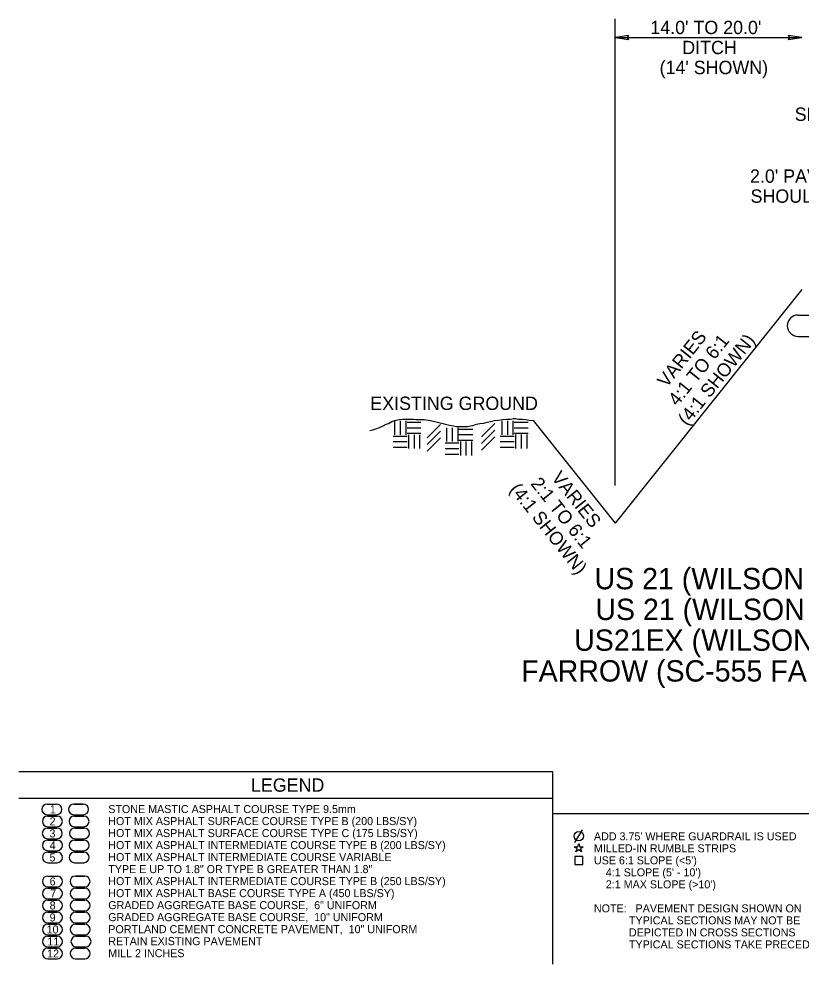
# Model space of a CAD drawing. Extents: x 2003207 to 2014043, y 843846 to 860154.
# Drawn here: x 2013805.7 to 2013864.3, y 844566 to 844636.8 of the extents above; entities that cross this region are included whole.
import ezdxf

# ---------------------------------------------------------------- set-up
doc = ezdxf.new("R2010")
doc.units = 0
for name, color, linetype in [('RD_EX_Road', 7, 'Continuous'), ('RD_EX_Road_txCode', 7, 'Continuous'), ('RD_QTY_ConcPave', 7, 'Continuous'), ('RD_QTY_Intermediate', 7, 'Continuous'), ('RD_QTY_Milling', 7, 'Continuous'), ('RD_QTY_PermVeg', 7, 'Continuous'), ('RD_QTY_Surf_Course', 7, 'Continuous'), ('RD_SHT_Bndy', 7, 'Continuous'), ('RD_TX_Misc2', 7, 'Continuous'), ('RD_TX_TypSect', 7, 'Continuous'), ('RD_XS_ExGround', 7, 'Continuous')]:
    doc.layers.add(name, color=color, linetype=linetype)

msp = doc.modelspace()

# ---------------------------------------------------------------- linework, layer by layer
at = {"layer": 'RD_EX_Road'}
for p, q in [((2013810.723, 844568.087), (2013810.023, 844568.087)), ((2013810.661, 844567.187), (2013809.961, 844567.187)), ((2013810.023, 844567.287), (2013810.723, 844567.287)), ((2013809.961, 844566.387), (2013810.661, 844566.387))]:
    msp.add_line(p, q, dxfattribs=at)
for centre, start, end in [((2013810.023, 844567.687), 90, 270), ((2013810.723, 844567.687), 270, 90), ((2013809.961, 844566.787), 90, 270), ((2013810.661, 844566.787), 270, 90)]:
    msp.add_arc(centre, 0.4, start, end, dxfattribs=at)
at = {"layer": 'RD_EX_Road_txCode'}
msp.add_line((2013847.384, 844575.107), (2013847.95, 844576.05), dxfattribs=at)
for points in [[(2013847.335, 844574.786), (2013847.589, 844574.786), (2013847.667, 844575.028), (2013847.746, 844574.786), (2013848, 844574.786), (2013847.795, 844574.637), (2013847.873, 844574.395), (2013847.667, 844574.544), (2013847.462, 844574.395), (2013847.54, 844574.637)], [(2013847.367, 844573.452), (2013847.967, 844573.452), (2013847.967, 844574.052), (2013847.367, 844574.052)]]:
    msp.add_lwpolyline(points, close=True, dxfattribs=at)
msp.add_circle((2013847.667, 844575.578), 0.35, dxfattribs=at)
at = {"layer": 'RD_QTY_ConcPave'}
for p, q in [((2013810.661, 844570.787), (2013809.961, 844570.787)), ((2013809.961, 844569.987), (2013810.661, 844569.987)), ((2013810.661, 844569.887), (2013809.961, 844569.887)), ((2013809.961, 844569.087), (2013810.661, 844569.087)), ((2013810.661, 844568.987), (2013809.961, 844568.987)), ((2013809.961, 844568.187), (2013810.661, 844568.187))]:
    msp.add_line(p, q, dxfattribs=at)
for centre, start, end in [((2013809.961, 844570.387), 90, 270), ((2013810.661, 844570.387), 270, 90), ((2013809.961, 844569.487), 90, 270), ((2013810.661, 844569.487), 270, 90), ((2013809.961, 844568.587), 90, 270), ((2013810.661, 844568.587), 270, 90)]:
    msp.add_arc(centre, 0.4, start, end, dxfattribs=at)
at = {"layer": 'RD_QTY_Intermediate'}
for p, q in [((2013810.582, 844575.287), (2013809.882, 844575.287)), ((2013809.882, 844574.487), (2013810.582, 844574.487)), ((2013810.582, 844574.387), (2013809.882, 844574.387)), ((2013809.882, 844573.587), (2013810.582, 844573.587)), ((2013810.65, 844572.587), (2013809.95, 844572.587)), ((2013809.95, 844571.787), (2013810.65, 844571.787)), ((2013810.661, 844571.687), (2013809.961, 844571.687)), ((2013809.961, 844570.887), (2013810.661, 844570.887))]:
    msp.add_line(p, q, dxfattribs=at)
for centre, start, end in [((2013809.882, 844574.887), 90, 270), ((2013810.582, 844574.887), 270, 90), ((2013809.882, 844573.987), 90, 270), ((2013810.582, 844573.987), 270, 90), ((2013809.95, 844572.187), 90, 270), ((2013810.65, 844572.187), 270, 90), ((2013809.961, 844571.287), 90, 270), ((2013810.661, 844571.287), 270, 90)]:
    msp.add_arc(centre, 0.4, start, end, dxfattribs=at)
at = {"layer": 'RD_QTY_Milling'}
for p, q in [((2013810.661, 844567.187), (2013809.961, 844567.187)), ((2013809.961, 844566.387), (2013810.661, 844566.387))]:
    msp.add_line(p, q, dxfattribs=at)
for centre, start, end in [((2013809.961, 844566.787), 90, 270), ((2013810.661, 844566.787), 270, 90)]:
    msp.add_arc(centre, 0.4, start, end, dxfattribs=at)
at = {"layer": 'RD_QTY_PermVeg'}
for p in [(2013864.392, 844616.536), (2013844.245, 844606.72)]:
    msp.add_line(p, (2013850.392, 844599.036), dxfattribs=at)
at = {"layer": 'RD_QTY_Surf_Course'}
for p, q in [((2013810.542, 844577.987), (2013809.842, 844577.987)), ((2013809.842, 844577.187), (2013810.542, 844577.187)), ((2013810.576, 844577.087), (2013809.876, 844577.087)), ((2013809.876, 844576.287), (2013810.576, 844576.287)), ((2013810.61, 844576.187), (2013809.91, 844576.187)), ((2013809.91, 844575.387), (2013810.61, 844575.387))]:
    msp.add_line(p, q, dxfattribs=at)
for centre, start, end in [((2013809.842, 844577.587), 90, 270), ((2013810.542, 844577.587), 270, 90), ((2013809.876, 844576.687), 90, 270), ((2013810.576, 844576.687), 270, 90), ((2013809.91, 844575.787), 90, 270), ((2013810.61, 844575.787), 270, 90)]:
    msp.add_arc(centre, 0.4, start, end, dxfattribs=at)
at = {"layer": 'RD_SHT_Bndy'}
for p, q in [((2013845.721, 844580.41), (2013805.721, 844580.41)), ((2013845.721, 844578.41), (2013845.721, 844580.41)), ((2013845.721, 844578.41), (2013805.721, 844578.41)), ((2013845.721, 844565.992), (2013845.721, 844578.41)), ((2013868.755, 844577.242), (2013845.755, 844577.242))]:
    msp.add_line(p, q, dxfattribs=at)
at = {"layer": 'RD_TX_Misc2'}
for p, q in [((2013864.098, 844614.63), (2013865.498, 844614.63)), ((2013864.098, 844613.03), (2013865.498, 844613.03)), ((2013807.842, 844577.987), (2013808.542, 844577.987)), ((2013809.842, 844577.987), (2013810.542, 844577.987)), ((2013807.842, 844577.187), (2013808.542, 844577.187)), ((2013807.876, 844577.087), (2013808.576, 844577.087)), ((2013809.842, 844577.187), (2013810.542, 844577.187)), ((2013809.876, 844577.087), (2013810.576, 844577.087)), ((2013807.871, 844576.187), (2013808.571, 844576.187)), ((2013807.876, 844576.287), (2013808.576, 844576.287)), ((2013809.876, 844576.287), (2013810.576, 844576.287)), ((2013809.91, 844576.187), (2013810.61, 844576.187)), ((2013807.871, 844575.387), (2013808.571, 844575.387)), ((2013807.882, 844575.287), (2013808.582, 844575.287)), ((2013809.882, 844575.287), (2013810.582, 844575.287)), ((2013809.91, 844575.387), (2013810.61, 844575.387)), ((2013807.882, 844574.487), (2013808.582, 844574.487)), ((2013807.882, 844574.387), (2013808.582, 844574.387)), ((2013809.882, 844574.487), (2013810.582, 844574.487)), ((2013809.882, 844574.387), (2013810.582, 844574.387)), ((2013807.882, 844573.587), (2013808.582, 844573.587)), ((2013809.882, 844573.587), (2013810.582, 844573.587)), ((2013807.882, 844572.587), (2013808.582, 844572.587)), ((2013809.95, 844572.587), (2013810.65, 844572.587)), ((2013807.882, 844571.787), (2013808.582, 844571.787)), ((2013807.882, 844571.687), (2013808.582, 844571.687)), ((2013809.95, 844571.787), (2013810.65, 844571.787)), ((2013809.961, 844571.687), (2013810.661, 844571.687)), ((2013807.882, 844570.887), (2013808.582, 844570.887)), ((2013807.882, 844570.787), (2013808.582, 844570.787)), ((2013809.961, 844570.887), (2013810.661, 844570.887)), ((2013809.961, 844570.787), (2013810.661, 844570.787)), ((2013807.882, 844569.987), (2013808.582, 844569.987)), ((2013809.961, 844569.987), (2013810.661, 844569.987)), ((2013807.882, 844569.887), (2013808.582, 844569.887)), ((2013809.961, 844569.887), (2013810.661, 844569.887)), ((2013807.882, 844569.087), (2013808.582, 844569.087)), ((2013807.882, 844568.987), (2013808.582, 844568.987)), ((2013809.961, 844569.087), (2013810.661, 844569.087)), ((2013809.961, 844568.987), (2013810.661, 844568.987)), ((2013807.882, 844568.187), (2013808.582, 844568.187)), ((2013807.882, 844568.087), (2013808.582, 844568.087)), ((2013809.961, 844568.187), (2013810.661, 844568.187)), ((2013810.023, 844568.087), (2013810.723, 844568.087)), ((2013807.882, 844567.287), (2013808.582, 844567.287)), ((2013807.882, 844567.187), (2013808.582, 844567.187)), ((2013809.961, 844567.187), (2013810.661, 844567.187)), ((2013810.023, 844567.287), (2013810.723, 844567.287)), ((2013807.882, 844566.387), (2013808.582, 844566.387)), ((2013809.961, 844566.387), (2013810.661, 844566.387))]:
    msp.add_line(p, q, dxfattribs=at)
for centre, radius, start, end in [((2013864.098, 844613.83), 0.8, 90, 270), ((2013807.842, 844577.587), 0.4, 90, 270), ((2013808.542, 844577.587), 0.4, 270, 90), ((2013809.842, 844577.587), 0.4, 90, 270), ((2013810.542, 844577.587), 0.4, 270, 90), ((2013807.876, 844576.687), 0.4, 90, 270), ((2013808.576, 844576.687), 0.4, 270, 90), ((2013809.876, 844576.687), 0.4, 90, 270), ((2013810.576, 844576.687), 0.4, 270, 90), ((2013807.871, 844575.787), 0.4, 90, 270), ((2013808.571, 844575.787), 0.4, 270, 90), ((2013809.91, 844575.787), 0.4, 90, 270), ((2013810.61, 844575.787), 0.4, 270, 90), ((2013807.882, 844574.887), 0.4, 90, 270), ((2013808.582, 844574.887), 0.4, 270, 90), ((2013809.882, 844574.887), 0.4, 90, 270), ((2013810.582, 844574.887), 0.4, 270, 90), ((2013807.882, 844573.987), 0.4, 90, 270), ((2013808.582, 844573.987), 0.4, 270, 90), ((2013809.882, 844573.987), 0.4, 90, 270), ((2013810.582, 844573.987), 0.4, 270, 90), ((2013807.882, 844572.187), 0.4, 90, 270), ((2013808.582, 844572.187), 0.4, 270, 90), ((2013809.95, 844572.187), 0.4, 90, 270), ((2013810.65, 844572.187), 0.4, 270, 90), ((2013807.882, 844571.287), 0.4, 90, 270), ((2013808.582, 844571.287), 0.4, 270, 90), ((2013809.961, 844571.287), 0.4, 90, 270), ((2013810.661, 844571.287), 0.4, 270, 90), ((2013807.882, 844570.387), 0.4, 90, 270), ((2013808.582, 844570.387), 0.4, 270, 90), ((2013809.961, 844570.387), 0.4, 90, 270), ((2013810.661, 844570.387), 0.4, 270, 90), ((2013807.882, 844569.487), 0.4, 90, 270), ((2013808.582, 844569.487), 0.4, 270, 90), ((2013809.961, 844569.487), 0.4, 90, 270), ((2013810.661, 844569.487), 0.4, 270, 90), ((2013807.882, 844568.587), 0.4, 90, 270), ((2013808.582, 844568.587), 0.4, 270, 90), ((2013809.961, 844568.587), 0.4, 90, 270), ((2013810.661, 844568.587), 0.4, 270, 90), ((2013807.882, 844567.687), 0.4, 90, 270), ((2013808.582, 844567.687), 0.4, 270, 90), ((2013810.023, 844567.687), 0.4, 90, 270), ((2013810.723, 844567.687), 0.4, 270, 90), ((2013807.882, 844566.787), 0.4, 90, 270), ((2013808.582, 844566.787), 0.4, 270, 90), ((2013809.961, 844566.787), 0.4, 90, 270), ((2013810.661, 844566.787), 0.4, 270, 90)]:
    msp.add_arc(centre, radius, start, end, dxfattribs=at)
at = {"layer": 'RD_TX_TypSect'}
for p, q in [((2013850.392, 844601.863), (2013850.392, 844636.824)), ((2013850.392, 844635.433), (2013864.392, 844635.433))]:
    msp.add_line(p, q, dxfattribs=at)
for points in [[(2013850.392, 844635.433), (2013851.431, 844635.283), (2013851.271, 844635.433), (2013851.431, 844635.583)], [(2013864.392, 844635.433), (2013863.354, 844635.583), (2013863.514, 844635.433), (2013863.354, 844635.283)]]:
    msp.add_lwpolyline(points, close=True, dxfattribs=at)
at = {"layer": 'RD_XS_ExGround'}
for p, q in [((2013833.875, 844606.7), (2013833.875, 844605.658)), ((2013834.292, 844606.7), (2013834.292, 844605.658)), ((2013834.709, 844606.7), (2013834.709, 844605.658)), ((2013834.805, 844606.603), (2013835.847, 844606.603)), ((2013834.805, 844606.186), (2013835.847, 844606.186)), ((2013836.311, 844605.441), (2013837.311, 844606.441)), ((2013837.766, 844606.186), (2013837.766, 844605.145)), ((2013838.182, 844606.186), (2013838.182, 844605.145)), ((2013838.599, 844606.186), (2013838.599, 844605.145)), ((2013840.379, 844605.514), (2013841.379, 844606.514)), ((2013841.902, 844606.705), (2013841.902, 844605.663)), ((2013842.319, 844606.705), (2013842.319, 844605.663)), ((2013842.735, 844606.705), (2013842.735, 844605.663)), ((2013842.832, 844606.608), (2013843.873, 844606.608)), ((2013842.832, 844606.191), (2013843.873, 844606.191)), ((2013833.763, 844605.561), (2013834.805, 844605.561)), ((2013834.805, 844605.77), (2013835.847, 844605.77)), ((2013834.909, 844605.666), (2013834.909, 844604.624)), ((2013835.326, 844605.666), (2013835.326, 844604.624)), ((2013835.743, 844605.666), (2013835.743, 844604.624)), ((2013836.311, 844604.941), (2013837.311, 844605.941)), ((2013836.311, 844604.441), (2013837.311, 844605.441)), ((2013838.696, 844606.089), (2013839.737, 844606.089)), ((2013838.696, 844605.673), (2013839.737, 844605.673)), ((2013840.379, 844605.014), (2013841.379, 844606.014)), ((2013840.379, 844604.514), (2013841.379, 844605.514)), ((2013841.79, 844605.566), (2013842.832, 844605.566)), ((2013842.832, 844605.775), (2013843.873, 844605.775)), ((2013842.936, 844605.67), (2013842.936, 844604.629)), ((2013843.353, 844605.67), (2013843.353, 844604.629)), ((2013843.769, 844605.67), (2013843.769, 844604.629)), ((2013833.763, 844605.145), (2013834.805, 844605.145)), ((2013833.763, 844604.728), (2013834.805, 844604.728)), ((2013837.654, 844605.048), (2013838.696, 844605.048)), ((2013838.696, 844605.256), (2013839.737, 844605.256)), ((2013838.8, 844605.152), (2013838.8, 844604.11)), ((2013839.216, 844605.152), (2013839.216, 844604.11)), ((2013839.633, 844605.152), (2013839.633, 844604.11)), ((2013841.79, 844605.15), (2013842.832, 844605.15)), ((2013841.79, 844604.733), (2013842.832, 844604.733)), ((2013837.654, 844604.631), (2013838.696, 844604.631)), ((2013837.654, 844604.214), (2013838.696, 844604.214))]:
    msp.add_line(p, q, dxfattribs=at)
msp.add_lwpolyline([(2013832.019, 844605.988), (2013832.239, 844606.024), (2013832.459, 844606.098), (2013832.751, 844606.208), (2013833.008, 844606.317), (2013833.227, 844606.464), (2013833.41, 844606.501), (2013833.667, 844606.647), (2013833.886, 844606.72), (2013834.216, 844606.794), (2013834.472, 844606.83), (2013834.765, 844606.83), (2013835.094, 844606.83), (2013835.277, 844606.83), (2013835.46, 844606.794), (2013835.68, 844606.794), (2013835.899, 844606.794), (2013836.082, 844606.794), (2013836.375, 844606.757), (2013836.558, 844606.72), (2013836.888, 844606.647), (2013837.181, 844606.574), (2013837.473, 844606.501), (2013837.656, 844606.464), (2013837.986, 844606.391), (2013838.279, 844606.317), (2013838.498, 844606.281), (2013838.681, 844606.281), (2013838.901, 844606.281), (2013839.121, 844606.281), (2013839.34, 844606.281), (2013839.56, 844606.317), (2013839.743, 844606.354), (2013839.999, 844606.464), (2013840.255, 844606.501), (2013840.548, 844606.537), (2013840.804, 844606.61), (2013841.061, 844606.647), (2013841.353, 844606.72), (2013841.646, 844606.757), (2013841.939, 844606.794), (2013842.268, 844606.83), (2013842.561, 844606.83), (2013842.781, 844606.867), (2013842.964, 844606.867), (2013843.147, 844606.83), (2013843.44, 844606.83), (2013843.696, 844606.794), (2013843.952, 844606.757), (2013844.245, 844606.72)], dxfattribs=at)

# ---------------------------------------------------------------- texts
at = {"layer": 'RD_EX_Road_txCode'}
for s, height, p in [('US 21 (WILSON BLVD.) STA. 679+87.94 TO STA. 686+30.40', 1.6, (2013848.85, 844594.081)), ('US 21 (WILSON BLVD.) STA. 725+42.01 TO STA. 727+53.48', 1.6, (2013848.913, 844591.775)), ('US21EX (WILSON BLVD.) 720+46.38 R2 TO STA. 721+51.38 R2', 1.6, (2013847.325, 844589.47)), ('FARROW (SC-555 FARROW ROAD) STA. 356+50.00 TO STA. 360+44.74', 1.6, (2013843.357, 844587.164)), ('LEGEND', 1, (2013823.11, 844578.91)), ('STONE MASTIC ASPHALT COURSE TYPE 9.5mm', 0.6, (2013812.417, 844577.31)), ('HOT MIX ASPHALT SURFACE COURSE TYPE B (200 LBS/SY)', 0.6, (2013812.417, 844576.41)), ('HOT MIX ASPHALT SURFACE COURSE TYPE C (175 LBS/SY)', 0.6, (2013812.417, 844575.51)), ("ADD 3.75' WHERE GUARDRAIL IS USED", 0.6, (2013848.808, 844575.268)), ('HOT MIX ASPHALT INTERMEDIATE COURSE TYPE B (200 LBS/SY)', 0.6, (2013812.417, 844574.61)), ('MILLED-IN RUMBLE STRIPS', 0.6, (2013848.808, 844574.368)), ('HOT MIX ASPHALT INTERMEDIATE COURSE VARIABLE ', 0.6, (2013812.417, 844573.71)), ("USE 6:1 SLOPE (<5')", 0.6, (2013848.808, 844573.468)), ('TYPE E UP TO 1.8" OR TYPE B GREATER THAN 1.8"', 0.6, (2013812.417, 844572.81)), ("    4:1 SLOPE (5' - 10')", 0.6, (2013848.808, 844572.568)), ('HOT MIX ASPHALT INTERMEDIATE COURSE TYPE B (250 LBS/SY)', 0.6, (2013812.417, 844571.91)), ("    2:1 MAX SLOPE (>10')", 0.6, (2013848.808, 844571.668)), ('HOT MIX ASPHALT BASE COURSE TYPE A (450 LBS/SY)', 0.6, (2013812.417, 844571.01)), ('GRADED AGGREGATE BASE COURSE,  6" UNIFORM', 0.6, (2013812.417, 844570.11)), ('NOTE:   PAVEMENT DESIGN SHOWN ON', 0.6, (2013848.808, 844569.868)), ('GRADED AGGREGATE BASE COURSE,  10" UNIFORM', 0.6, (2013812.417, 844569.21)), (' TYPICAL SECTIONS MAY NOT BE ', 0.6, (2013851.208, 844568.968)), ('PORTLAND CEMENT CONCRETE PAVEMENT,  10" UNIFORM', 0.6, (2013812.417, 844568.31)), (' DEPICTED IN CROSS SECTIONS', 0.6, (2013851.208, 844568.068)), ('RETAIN EXISTING PAVEMENT', 0.6, (2013812.417, 844567.41)), (' TYPICAL SECTIONS TAKE PRECEDENCE', 0.6, (2013851.208, 844567.168)), ('MILL 2 INCHES', 0.6, (2013812.417, 844566.51))]:
    msp.add_text(s, height=height, dxfattribs=at).set_placement(p)
at = {"layer": 'RD_TX_Misc2'}
for s, p in [('1', (2013808.039, 844577.287)), ('2', (2013808.022, 844576.387)), ('3', (2013808.011, 844575.487)), ('4', (2013808.023, 844574.587)), ('5', (2013808.011, 844573.687)), ('6', (2013808.023, 844571.887)), ('7 ', (2013808.066, 844570.987)), ('8', (2013808.023, 844570.087)), ('9', (2013808.023, 844569.187)), ('10', (2013807.796, 844568.287)), ('11', (2013807.852, 844567.387)), ('12', (2013807.835, 844566.487))]:
    msp.add_text(s, height=0.6, dxfattribs=at).set_placement(p)
at = {"layer": 'RD_TX_TypSect'}
for s, p in [("14.0' TO 20.0'", (2013853.034, 844635.683)), ('DITCH', (2013855.428, 844634.183)), ("(14' SHOWN)", (2013853.727, 844632.683)), ('SHOULDER', (2013863.853, 844629.183)), ("2.0' PAVED", (2013860.503, 844624.544)), ('SHOULDER', (2013860.542, 844623.044)), ('EXISTING GROUND', (2013832.053, 844607.517))]:
    msp.add_text(s, height=1, dxfattribs=at).set_placement(p)
for s, rotation, p in [('VARIES', 51.34019, (2013854.247, 844609.135)), ('4:1 TO 6:1', 51.34019, (2013855.06, 844607.75)), ('(4:1 SHOWN)', 51.34019, (2013855.798, 844606.271)), ('VARIES', 308.65981, (2013845.575, 844602.427)), ('(4:1 SHOWN)', 308.65981, (2013842.44, 844601.543)), ('2:1 TO 6:1', 308.65981, (2013844.015, 844601.976))]:
    msp.add_text(s, height=1, rotation=rotation, dxfattribs=at).set_placement(p)

doc.saveas('drawing.dxf')
